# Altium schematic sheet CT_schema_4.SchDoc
size 372 x 317 mm
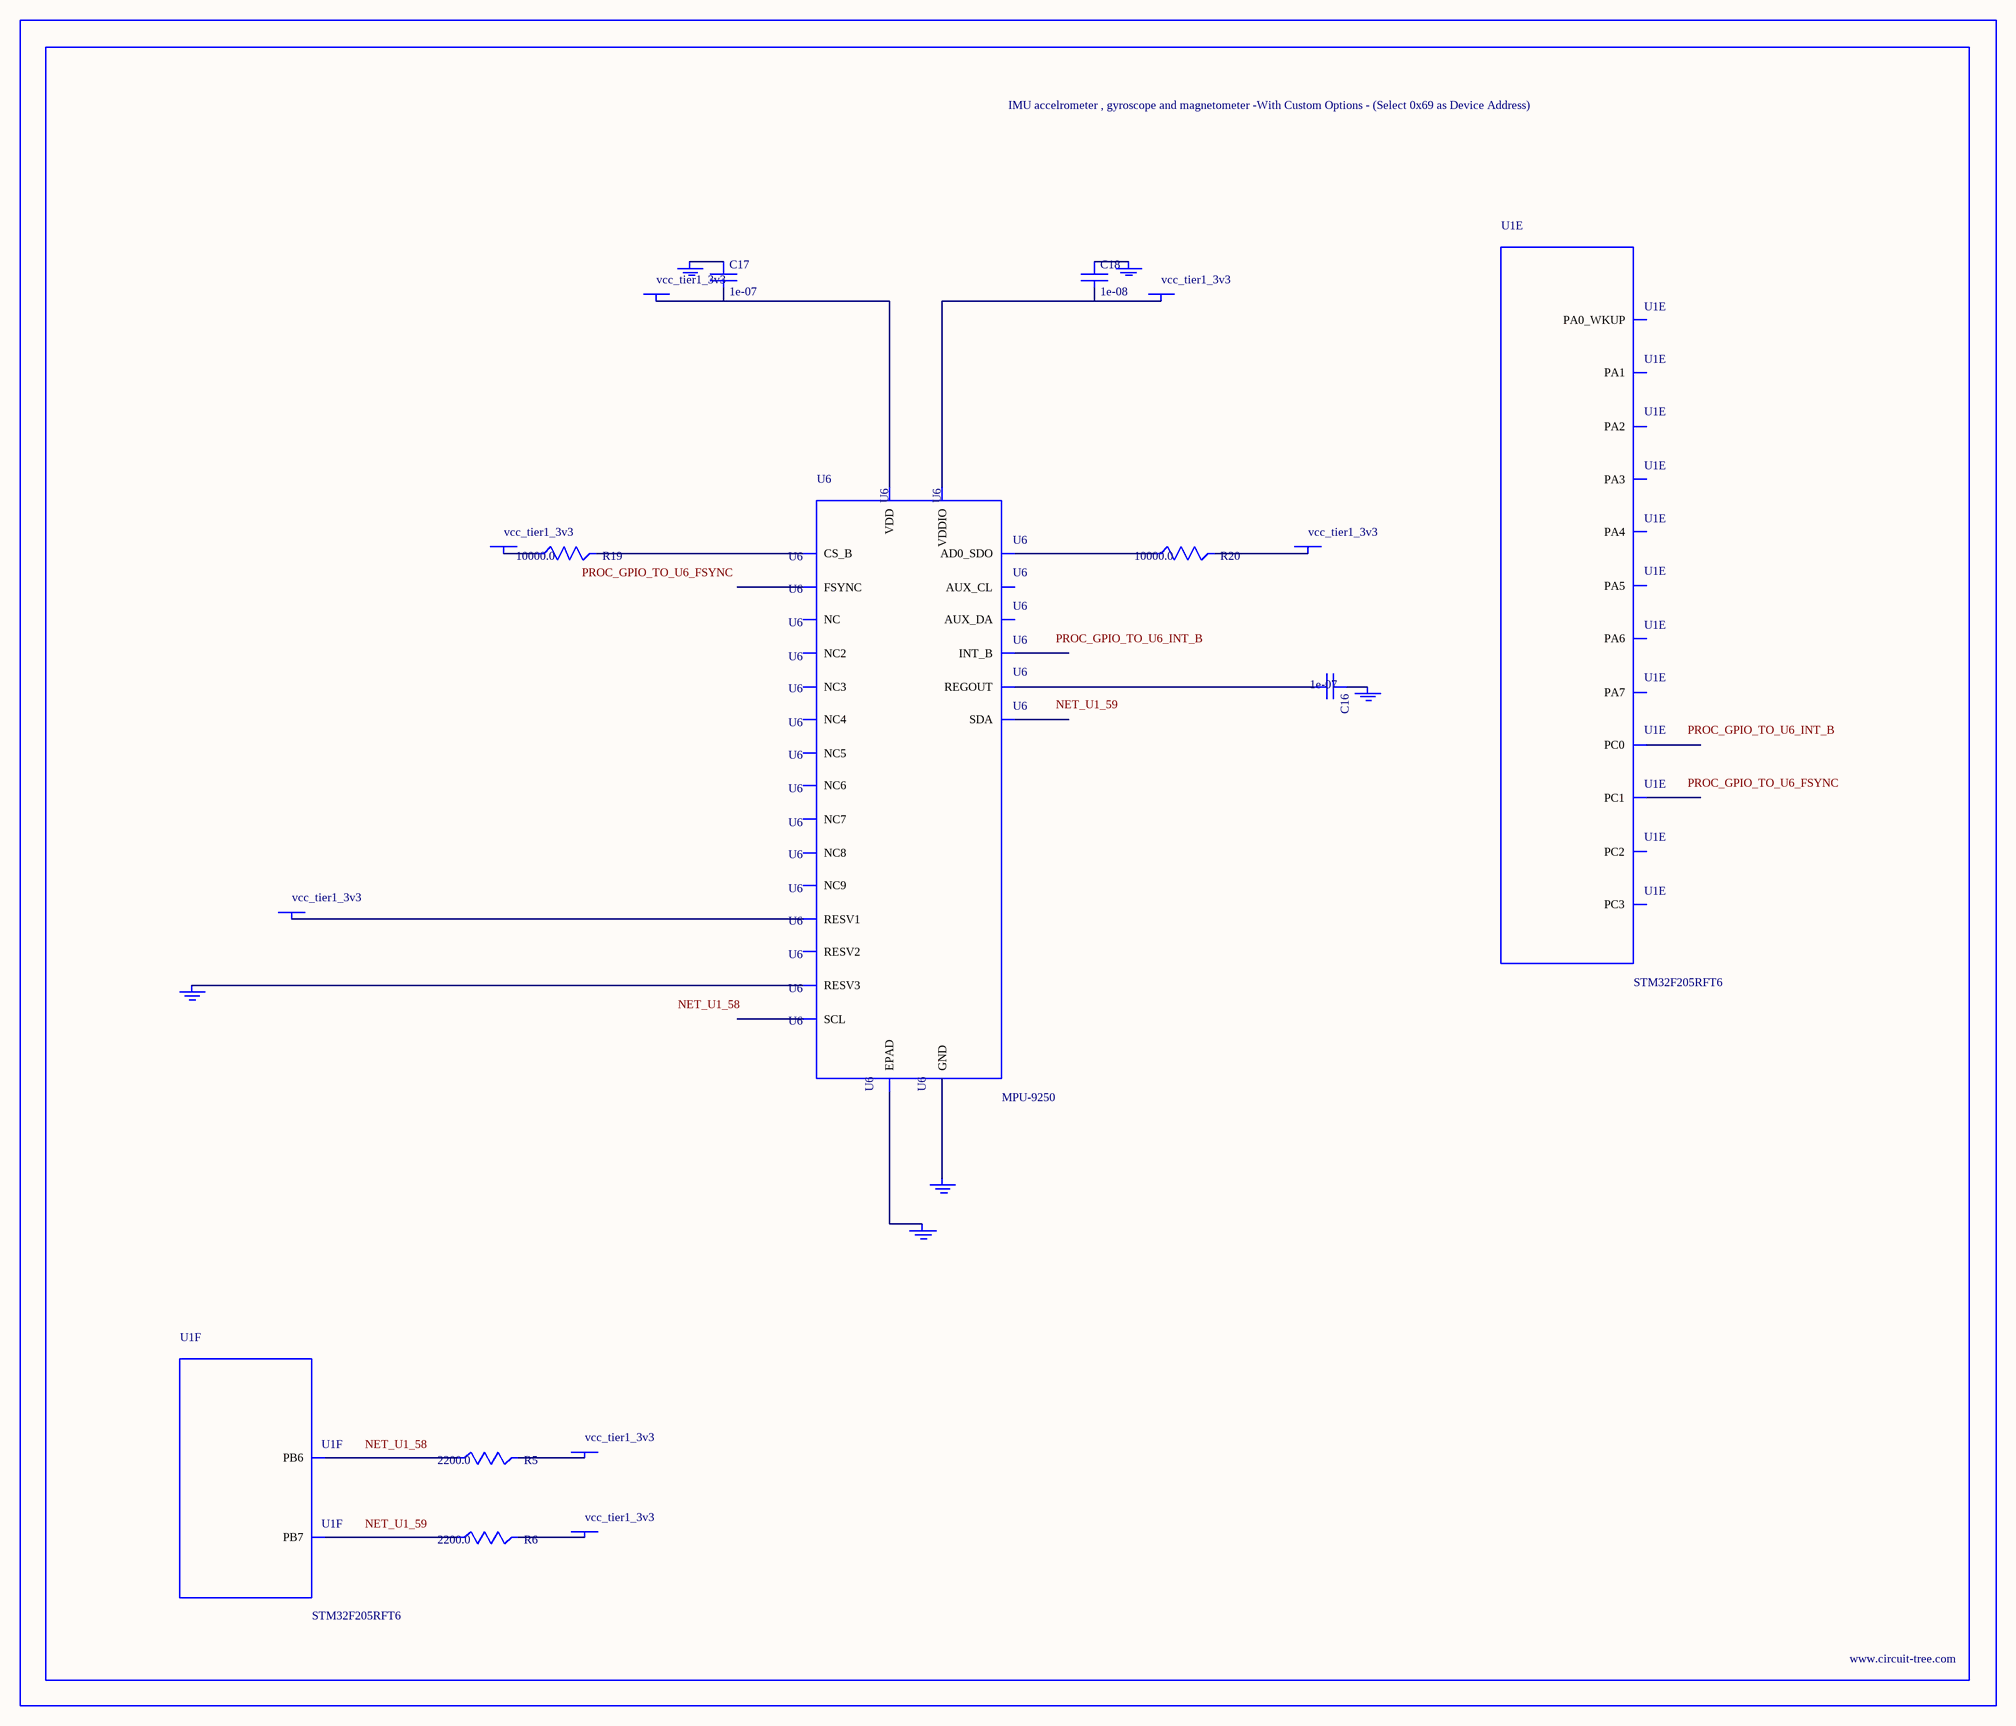
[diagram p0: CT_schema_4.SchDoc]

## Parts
BORDER3  (no value)
C16  1e-07  [C0402]
C17  1e-07  [C0402]
C18  1e-08  [C0402]
GND_INSTANCE_3_0  (no value)
GND_INSTANCE_3_1  (no value)
GND_INSTANCE_3_2  (no value)
GND_INSTANCE_3_3  (no value)
GND_INSTANCE_3_4  (no value)
GND_INSTANCE_3_5  (no value)
POWER_INSTANCE_3_0  vcc_tier1_3v3
POWER_INSTANCE_3_1  vcc_tier1_3v3
POWER_INSTANCE_3_2  vcc_tier1_3v3
POWER_INSTANCE_3_3  vcc_tier1_3v3
POWER_INSTANCE_3_4  vcc_tier1_3v3
POWER_INSTANCE_3_5  vcc_tier1_3v3
POWER_INSTANCE_3_6  vcc_tier1_3v3
R5  2200.0  [R0603]
R6  2200.0  [R0603]
R19  10000.0  [R0603]
R20  10000.0  [R0603]
U1  STM32F205RFT6  [LQFP64]  (parts E,F of 7)
U6  MPU-9250  [QFN24_2]

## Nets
NetC16_1: C16.1 GND_INSTANCE_3_1.0(GND)
NetC16_2: C16.2 U6.10(REGOUT)
NetC17_1: C17.1 GND_INSTANCE_3_2.0(GND)
NetC17_2: C17.2 POWER_INSTANCE_3_3.0(PWR) U6.13(VDD)
NetC18_1: C18.1 GND_INSTANCE_3_0.0(GND)
NetC18_2: C18.2 POWER_INSTANCE_3_1.0(PWR) U6.8(VDDIO)
NetGND_INSTANCE_3_3_0: GND_INSTANCE_3_3.0(GND) U6.20(RESV3)
NetGND_INSTANCE_3_4_0: GND_INSTANCE_3_4.0(GND) U6.25(EPAD)
NetGND_INSTANCE_3_5_0: GND_INSTANCE_3_5.0(GND) U6.18(GND)
NetPOWER_INSTANCE_3_0_0: POWER_INSTANCE_3_0.0(PWR) U6.1(RESV1)
NetPOWER_INSTANCE_3_2_0: POWER_INSTANCE_3_2.0(PWR) R20.2
NetPOWER_INSTANCE_3_4_0: POWER_INSTANCE_3_4.0(PWR) R19.1
NetPOWER_INSTANCE_3_5_0: POWER_INSTANCE_3_5.0(PWR) R5.2
NetPOWER_INSTANCE_3_6_0: POWER_INSTANCE_3_6.0(PWR) R6.2
NetR5_1: R5.1 U1.58(PB6)
NetR6_1: R6.1 U1.59(PB7)
NetR19_2: R19.2 U6.22(CS_B)
NetR20_1: R20.1 U6.9(AD0_SDO)

Not connected (* = marked no-connect by the designer): U1 8(PC0) 9(PC1) 10(PC2) 11(PC3) 14(PA0_WKUP) 15(PA1) 16(PA2) 17(PA3) 20(PA4) 21(PA5) 22(PA6) 23(PA7); U6 2(NC) 3(NC2) 4(NC3) 5(NC4) 6(NC5) 7(AUX_CL) 11(FSYNC) 12(INT_B) 14(NC6) 15(NC7) 16(NC8) 17(NC9) 19(RESV2) 21(AUX_DA) 23(SCL) 24(SDA)

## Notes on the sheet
- Labels drawn without touching a wire or pin: NET_U1_58, NET_U1_59, PROC_GPIO_TO_U6_FSYNC, PROC_GPIO_TO_U6_INT_B

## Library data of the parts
BORDER3 = BORDER_PAGE3
C16 C17 = C0402C104K3RACTU
C18 = C0402C103K3RAC
GND_INSTANCE_3_0-GND_INSTANCE_3_5 = GND
POWER_INSTANCE_3_0-POWER_INSTANCE_3_6 = PWR
R5 R6 = RC0603JR-072K2L
R19 R20 = RC0603JR-0710KL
